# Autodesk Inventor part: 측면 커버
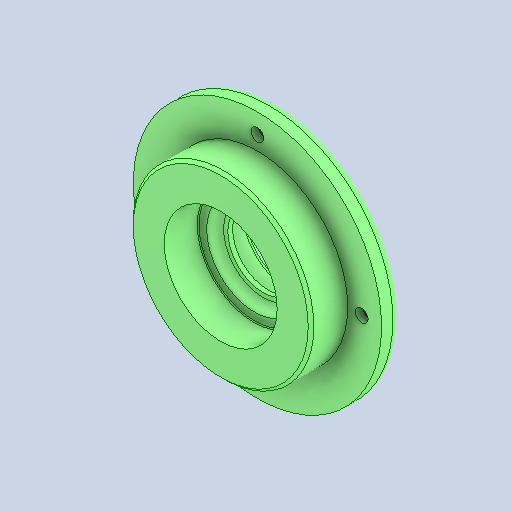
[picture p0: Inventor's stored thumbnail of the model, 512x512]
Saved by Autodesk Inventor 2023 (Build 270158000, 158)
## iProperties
Created: 2025-04
Part Number: 측면 커버
Material: 알루미늄 6061
Document SubType Name: Modeling
Designer: Admin
Density: 2.71 g/cm^3
Appearance: 기본값
Company: 한국ATC센터
Author: jhkim
Revision Number: 1
Sending System: Autodesk Inventor 2026
Preprocessor: ST-DEVELOPER v20.1
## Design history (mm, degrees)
feature "솔리드1"
node "솔리드2"
